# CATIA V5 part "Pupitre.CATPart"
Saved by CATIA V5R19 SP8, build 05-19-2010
Part number: Pupitre
Revision: 1
Definition: part definition
Nomenclature: __GRANITE__0
Source: Unknown
Description: NOT SPECIFIED
Bounding box of the stored display mesh (mm): x -66.155 to 398.608, y -68.59 to 38.525, z -361.735 to 371.266
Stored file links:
  C:\Users\rphgr\Desktop\0_Tapis_TC520B_vitesse\Pupitre.CATPart
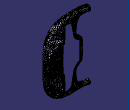
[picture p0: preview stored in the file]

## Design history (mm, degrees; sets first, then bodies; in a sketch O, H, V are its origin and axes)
AxisSystem1: origin (0, 0, 0), X (1, 0, 0), Y (0, 1, 0), Z (0, 0, 1)
Body1 "MANIFOLD_SOLID_BREP #467697" (main body)
  Solid1: solid without history
  Plane1: type 3Points, Element1 vertex [face of Solid1 | face of Solid1 | face of Solid1 | face of Solid1], Element2 vertex [face of Solid1 | face of Solid1 | face of Solid1 | face of Solid1], Element3 vertex [face of Solid1 | face of Solid1 | face of Solid1 | face of Solid1]
  Split1: SplitPlane Plane1
  Mirror1: of the body so far, about face of Split1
